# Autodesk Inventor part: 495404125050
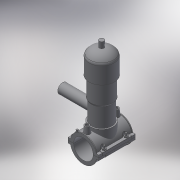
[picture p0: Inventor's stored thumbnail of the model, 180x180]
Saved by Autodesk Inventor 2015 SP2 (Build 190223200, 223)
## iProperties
Created: 2017-07
Part Number: 495404125050
Material: Generic
Description: PLASSON TAPPING VALVE 125-50
Document SubType Name: Modeling
Designer: KIM
Density: 1 g/cm^3
Appearance: Default
Author: KIM
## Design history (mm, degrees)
derived "495404-4954S4.ipt"
feature "Solid1::495404-4954S4.ipt"
feature "Solid2::495404-4954S4.ipt"
tag "TaggingFeature1"
body "Solid1"
body "Solid2"
other parameters: "d0" = 125, "d2" = 162, "d3" = 31.25, "d4" = 118, "d5" = 0, "d6" = 0.1, "d8" = 0, "d19" = 6, "d20" = 6, "d21" = 70.8, "d23" = 0, "d24" = 35.4, "d26" = 0, "d27" = 3, "d28" = 3, "d29" = 3, "d30" = 41.66667, "d31" = 6, "d32" = 0, "d33" = 0, "d34" = 0.6, "d40" = 81.25, "d47" = 129.125, "d70" = 15, "d72" = 0, "d73" = 6, "d75" = 5, "d76" = 0, "d77" = 6.25, "d78" = 92.5, "d79" = 15, "d80" = 47.2, "d82" = 5 deg, "d84" = 4, "d85" = 14, "d86" = 0, "d87" = 3, "d88" = 0, "d89" = 1, "d90" = 1, "d91" = 94.4, "d92" = 0, "d93" = 0.5, "d94" = 65.78947, "d96" = 160.9375, "d97" = 2.36, "d98" = 0, "d120" = 140 deg, "d121" = 24.228, "d122" = 20 deg, "d123" = 312.5, "d124" = 93.75, "d126" = 0, "d143" = 128.75, "d145" = 24.03846, "d149" = 1.875, "d150" = 26.44231, "d153" = 118, "d154" = 0, "d156" = 78.125, "d157" = 160 deg, "d159" = 6.25, "d161" = 1.875, "d162" = 70.8, "d163" = 0, "d164" = 62.5, "d167" = 12.5, "d168" = 76.21951, "d170" = 3, "d172" = 0, "d173" = 1, "d175" = 62.5, "d176" = 20 deg, "d177" = 8.75, "d178" = 31.25, "d180" = 0, "d183" = 12.5, "d184" = 7, "d185" = 38.35, "d186" = 38.35, "d187" = 78.125, "d188" = 9.375, "d189" = 8.75, "d190" = 0, "d191" = 117.1875, "d193" = 6.8, "d194" = 2.95, "d195" = 90 deg, "d197" = 0, "d199" = 0, "d205" = 14.64, "d206" = 81.33333, "d207" = 244, "d208" = 224.48, "d209" = 207.4, "d210" = 200.08, "d211" = 146.4, "d212" = 85.4, "d213" = 65.88, "d214" = 73.2, "d216" = 19.52, "d217" = 70.76, "d218" = 80.52, "d220" = 125, "d222" = 0, "d223" = 156.25, "d224" = 152, "d225" = 51, "d229" = 152, "d230" = 0, "d_" = 125, "B_" = 162, "H_" = 152, "L_" = 118, "d_t" = 6, "H_1" = 51, "H_2" = 244, "d148" = 1.875, "d160" = 1.875, "d169" = 3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
